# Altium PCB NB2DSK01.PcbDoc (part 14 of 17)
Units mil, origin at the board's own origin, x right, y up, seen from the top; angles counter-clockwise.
Board outline 11815 x 6500.03 mil, 8 copper layers (Top Layer, MidLayer1, MidLayer2, GND, PWR, MidLayer3, MidLayer4, Bottom Layer), stack 74.62 mil thick; 798 components, 1002 nets, 3927 pads, 3182 vias.
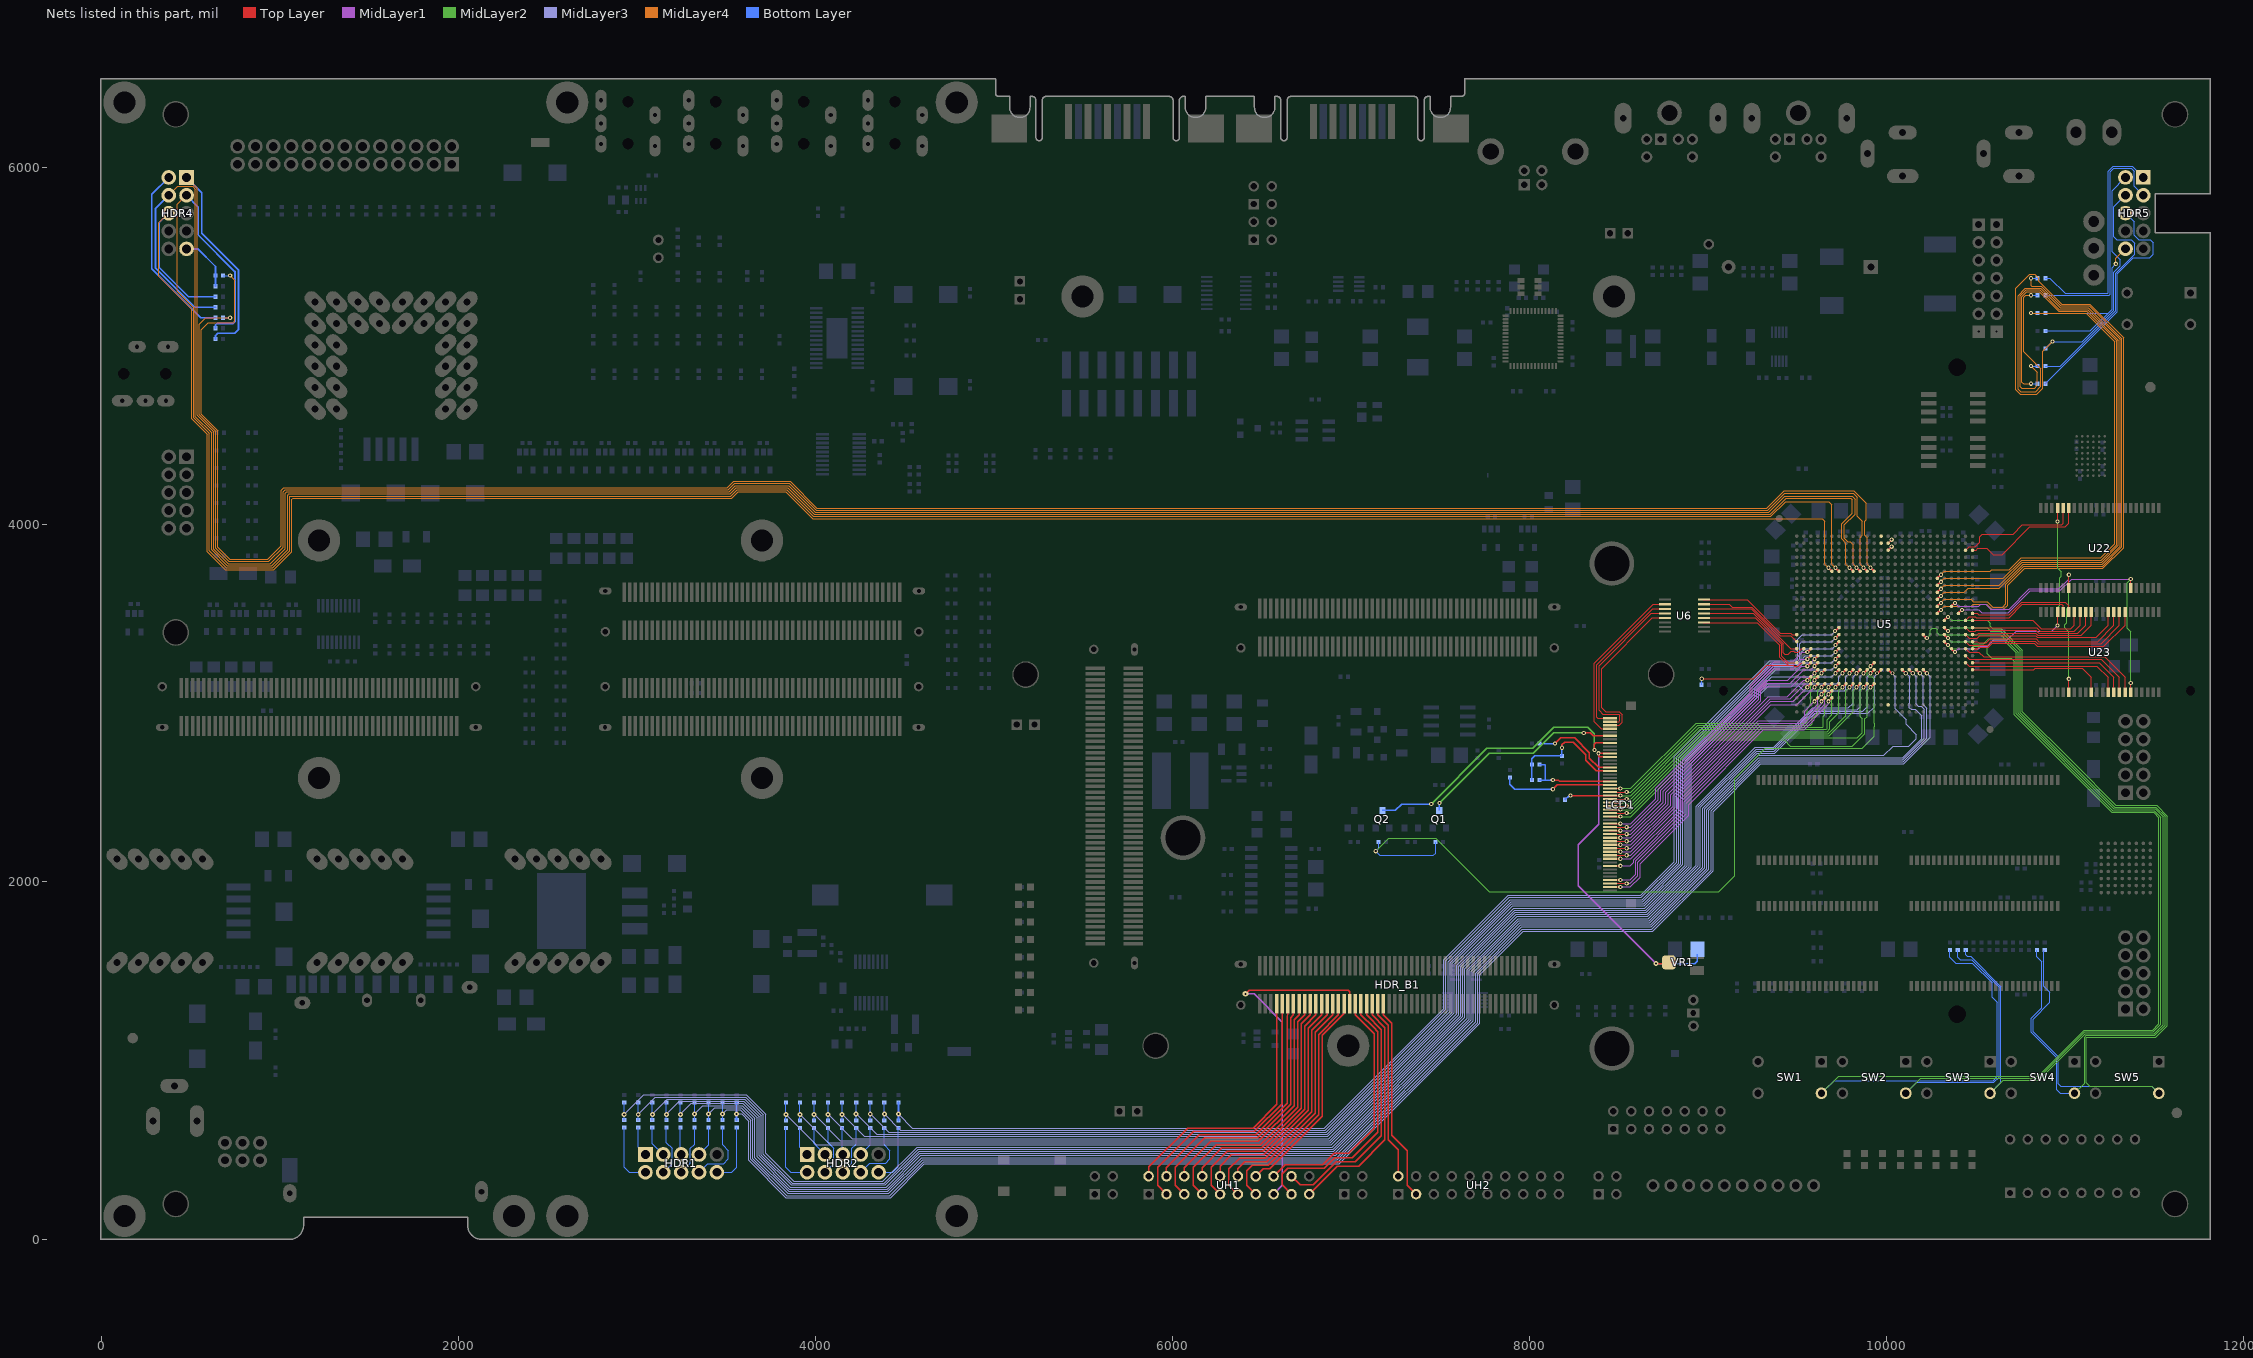
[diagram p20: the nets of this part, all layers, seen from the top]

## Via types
v1: diameter 23.62, hole 11.81, Top Layer to Bottom Layer, tented both sides, 1950 vias
v2: diameter 27.56, hole 11.81, Top Layer to Bottom Layer, tented both sides, 679 vias
v3: diameter 23.62, hole 11.81, Top Layer to Bottom Layer, 194 vias
v4: diameter 31.5, hole 11.81, Top Layer to Bottom Layer, tented both sides, 178 vias
v5: diameter 21.65, hole 11.81, Top Layer to Bottom Layer, tented both sides, 67 vias
v6: diameter 23.62, hole 11.81, Top Layer to Bottom Layer, tented bottom, 53 vias
v7: diameter 26, hole 11.81, Top Layer to Bottom Layer, tented both sides, 21 vias
v8: diameter 26, hole 11.81, Top Layer to Bottom Layer, 13 vias
v9: diameter 28, hole 11.81, Top Layer to Bottom Layer, 8 vias
v10: diameter 25.59, hole 11.81, Top Layer to Bottom Layer, tented both sides, 7 vias
v11: diameter 39.37, hole 11.81, Top Layer to Bottom Layer, tented both sides, 5 vias
v12: diameter 30, hole 11.81, Top Layer to Bottom Layer, 3 vias
v13: diameter 30, hole 11.81, Top Layer to Bottom Layer, tented both sides, 2 vias
v14: diameter 23, hole 11.81, Top Layer to Bottom Layer, tented both sides, 1 vias
v15: diameter 26.56, hole 11.81, Top Layer to Bottom Layer, tented both sides, 1 vias

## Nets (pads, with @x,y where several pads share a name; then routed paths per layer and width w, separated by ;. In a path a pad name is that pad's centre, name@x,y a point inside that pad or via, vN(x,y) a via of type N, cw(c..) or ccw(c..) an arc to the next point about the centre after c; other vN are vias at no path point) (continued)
SRAM.D19: U5.Y26 U23.10 | length 772.5
  Top Layer w5: U5.Y26@10480.32,3188.98 10543.31,3188.98 10562.99,3188.98 10822.83,3188.98 10830.71,3196.85 11094.49,3196.85 11145.67,3145.67 U23.10@11145.67,3062.99
SRAM.D20: U5.W25 U23.13 | length 916.1
  Top Layer w5: U5.W25@10440.95,3228.35 10460.63,3208.66 10543.31,3208.66 10562.99,3208.66 11177.17,3208.66 11240.16,3145.67 U23.13@11240.16,3062.99
SRAM.D21: U5.W26 U23.14 | length 908.3
  Top Layer w5: U5.W26@10480.32,3228.35 10543.31,3228.35 10562.99,3228.35 11188.98,3228.35 11271.66,3145.67 U23.14@11271.65,3062.99
SRAM.D22: U5.V25 U23.15 | length 997
  Top Layer w5: U5.V25@10440.95,3267.72 10462.5,3246.16 10541.44,3246.16 10543.31,3248.03 10562.99,3248.03 11200.79,3248.03 11303.15,3145.67 U23.15@11303.15,3062.99
SRAM.D23: U5.U25 U23.16 | length 1043.2
  Top Layer w5: U5.U25@10440.95,3307.09 10460.63,3287.4 10516.39,3287.4 10543.34,3260.45 11219.86,3260.45 11334.65,3145.67 U23.16@11334.65,3062.99
SRAM.D24: U5.U26 U23.29 | length 998.3
  Top Layer w5: U5.U26@10480.32,3307.09 10507.87,3307.09 10515.75,3314.96 10567.6,3314.96 10590.09,3337.45 10824.72,3337.45 10843.27,3318.9 11216.54,3318.9 11334.65,3437.01 U23.29@11334.65,3511.81
SRAM.D25: U5.T25 U23.30 | length 1001.4
  Top Layer w5: U5.T25@10440.95,3346.46 10460.63,3326.77 10543.31,3326.77 10562.99,3326.77 10565.27,3326.77 10585.95,3347.45 10832.44,3347.45 10845.24,3334.65 11200.79,3334.65 11303.15,3437.01 U23.30@11303.15,3511.81
SRAM.D26: U5.T26 U23.31 | length 922.6
  Top Layer w5: U5.T26@10480.32,3346.46 10507.87,3346.46 10515.75,3338.58 10543.31,3338.58 10556.81,3338.58 10579.68,3361.45 10837.06,3361.45 10852.06,3346.46 11181.1,3346.46 11271.65,3437.01 U23.31@11271.65,3511.81
SRAM.D27: U5.R25 U23.32 | length 918
  Top Layer w5: U5.R25@10440.95,3385.83 10460.63,3366.14 10507.87,3366.14 10519.69,3377.95 10543.31,3377.95 10562.99,3377.95 10834.65,3377.95 10842.52,3370.08 11173.23,3370.08 11240.16,3437.01 U23.32@11240.16,3511.81
SRAM.D28: U5.R26 U23.35 | length 771.1
  Top Layer w5: U5.R26@10480.32,3385.83 10507.87,3385.83 10515.75,3393.7 10543.31,3393.7 10562.99,3393.7 10834.65,3393.7 10846.46,3381.89 11090.55,3381.89 11145.67,3437.01 U23.35@11145.67,3511.81
SRAM.D29: U5.P25 U23.36 | length 782.3
  Top Layer w5: U5.P25@10440.95,3425.2 10460.63,3405.51 10496.06,3405.51 10500,3409.45 10543.31,3409.45 10562.99,3409.45 10834.65,3409.45 10850.39,3393.7 11070.87,3393.7 11114.17,3437.01 U23.36@11114.17,3511.81
SRAM.D30: U5.P26 U23.37 | length 698.4
  Top Layer w5: U5.P26@10480.32,3425.2 10543.31,3425.2 10562.99,3425.2 10838.58,3425.2 10858.27,3405.51 11051.18,3405.51 11082.68,3437.01 U23.37@11082.68,3511.81
SRAM.D31: U5.N26 U23.38 | length 673.4
  Top Layer w5: U5.N26@10480.32,3464.57 10543.31,3464.57 10562.99,3464.57 10818.9,3464.57 10866.14,3417.32 11031.5,3417.32 11051.18,3437.01 U23.38@11051.18,3511.81
SRAM.NBE0: U5.C26 U22.39 | length 717
  Top Layer w5: U5.C26@10480.32,3858.27 10500,3858.27 10510.81,3869.08 10560.78,3869.08 10595.86,3834 10647,3834 10801.19,3988.19 11000,3988.19 11019.69,4007.87 U22.39@11019.69,4094.49
SRAM.NBE1: U5.C25 U22.40 | length 714.3
  Top Layer w5: U5.C25@10440.95,3858.27 10460.63,3877.95 10496.06,3877.95 10519.69,3901.58 10519.69,3933.07 10535.43,3948.82 10543.31,3948.82 10562.99,3948.82 10708.66,3948.82 10759.84,4000 10980.32,4000 10988.19,4007.87 U22.40@10988.19,4094.49
SRAM.NBE2: U5.M26 U23.39 | length 615.6
  Top Layer w5: U5.M26@10480.32,3503.94 10507.87,3503.94 10515.75,3496.06 10543.31,3496.06 10562.99,3496.06 10685.04,3496.06 10755.91,3566.93 11000,3566.93 11019.69,3547.24 U23.39@11019.69,3511.81
SRAM.NBE3: U5.N25 U23.40 | length 626.7
  Top Layer w5: U5.N25@10440.95,3464.57 10460.63,3484.25 10496.06,3484.25 10500,3480.32 10543.31,3480.32 10562.99,3480.32 10685.04,3480.32 10759.84,3555.12 10980.32,3555.12 10988.19,3547.24 U23.40@10988.19,3511.81
SRAM.NCS: U5.L23 U22.6 U23.6 | length 1535.7
  Top Layer w5: U23.6@11019.69,3062.99 v1(11019.69,3137.8) ; U22.6@11019.69,3645.67 v1(11019.69,3720.47)
  Top Layer w7.87: U5.L23@10362.2,3543.31 v1(10381.89,3562.99)
  MidLayer1 w5: v1(10381.89,3562.99) 10401.58,3543.31 10515.75,3543.31 10527.56,3555.12 10543.31,3555.12 10555.12,3555.12 10582.68,3527.56 10685.04,3527.56 10799.21,3641.73 10964.57,3641.73 11019.69,3696.85 v1(11019.69,3720.47)
  MidLayer2 w5: v1(11019.69,3137.8) 11019.69,3401.58 10996.07,3425.2 10996.07,3440.95 11007.88,3452.76 11007.88,3531.5 11019.69,3543.31 v1(11019.69,3720.47)
SRAM.NOE: U5.U23 U22.41 U23.41 | length 1413.2
  Top Layer w5: v1(10956.7,3437.01) U23.41@10956.69,3511.81 ; v1(10956.69,4019.69) U22.41@10956.69,4094.49
  Top Layer w7.87: U5.U23@10362.2,3307.09 v1(10381.89,3287.4)
  MidLayer1 w5: v1(10381.89,3287.4) 10401.58,3307.09 10515.75,3307.09 ; 10515.75,3307.09 10527.56,3318.9 10543.31,3318.9 10562.99,3318.9 10600.55,3356.45 10675.35,3356.45 10724.41,3405.51 10925.2,3405.51 v1(10956.7,3437.01)
  MidLayer2 w5: v1(10956.7,3437.01) 10956.7,3539.37 10968.51,3551.18 10968.51,3704.73 10976.38,3712.6 10976.38,3736.22 10956.69,3755.91 v1(10956.69,4019.69)
SRAM.NWE: U5.M24 U22.17 U23.17 | length 1758.9
  Top Layer w5: U23.17@11366.14,3062.99 v1(11366.14,3114.17) ; U22.17@11366.14,3645.67 v1(11366.14,3696.85)
  Top Layer w7.87: U5.M24@10401.58,3503.94 v1(10421.26,3523.62)
  MidLayer1 w5: v1(10421.26,3523.62) 10515.75,3523.62 10531.5,3507.87 10543.31,3507.87 10562.99,3507.87 10681.1,3507.87 10803.15,3629.92 10968.5,3629.92 11035.43,3696.85 v1(11366.14,3696.85)
  MidLayer2 w5: v1(11366.14,3114.17) 11366.14,3401.58 11346.46,3421.26 11346.46,3677.17 v1(11366.14,3696.85)
SW0: R153.2 SW1.3 U5.T22 | length 6921.8
  Top Layer w7.87: U5.T22@10322.83,3346.46 v1(10342.52,3326.77)
  MidLayer2 w5: SW1.3@9633.86,816.93 9730.32,913.39 10847.1,913.39 11104.62,1170.9 11489.53,1170.9 11523.62,1204.99 11523.62,2359.91 11494.23,2389.3 11260.31,2389.3 10996.06,2653.54 10712.6,2937.01 10712.6,3237.5 10698.41,3251.68 10588.75,3251.68 10562.99,3277.44 10562.99,3318.9 10543.31,3318.9 10484.25,3318.9 10472.44,3307.09 10362.21,3307.09 v1(10342.52,3326.77)
  Bottom Layer w5: SW1.3@9633.86,816.93 9704.88,887.95 10596.31,887.95 10619.61,911.25 10619.61,1326 10590.5,1355.11 10590.5,1435.17 10479.65,1546.02 10385.98,1546.02 10353.41,1578.6 R153.2@10353.41,1618.11
SW1: R154.2 SW2.3 U5.R22 | length 6013
  Top Layer w7.87: U5.R22@10322.83,3385.83 v1(10342.52,3366.14)
  MidLayer2 w5: SW2.3@10106.3,816.93 10190.95,901.58 10849.44,901.58 11108.76,1160.9 11493.67,1160.9 11535.43,1202.66 11535.43,2362.24 11498.37,2399.3 11266.06,2399.3 10724.41,2940.95 10724.41,3283.47 10646.42,3361.45 10570.12,3361.45 10543.31,3334.65 10484.25,3334.65 10472.44,3346.46 10362.21,3346.46 v1(10342.52,3366.14)
  Bottom Layer w5: SW2.3@10106.3,816.93 10167.32,877.95 10600.45,877.95 10629.61,907.11 10629.61,1410.2 10474.7,1565.11 10410.89,1565.11 10397.7,1578.3 R154.2@10397.7,1618.11
SW2: R155.1 SW3.3 U5.R19 | length 5246.7
  Top Layer w7.87: U5.R19@10204.72,3385.83 v1(10224.41,3366.14)
  MidLayer2 w5: v1(10224.41,3366.14) 10244.09,3385.83 10244.09,3409.84 10255.91,3421.65 10274.02,3421.65 10283.07,3412.6 10283.07,3396.33 10293.58,3385.83 10543.31,3385.83 10562.99,3385.83 10637.8,3385.83 10736.22,3287.4 10736.22,2944.88 11019.69,2661.42 11271.8,2409.3 11502.52,2409.3 11547.24,2364.57 11547.24,1200.33 11497.82,1150.9 11112.9,1150.9 10851.77,889.77 10651.58,889.77 SW3.3@10578.74,816.93
  Bottom Layer w5: R155.1@10441.99,1618.11 10441.99,1593.01 10451,1584 10469.95,1584 10639.61,1414.35 10639.61,877.8 SW3.3@10578.74,816.93
SW3: R156.2 SW4.3 U5.P22 | length 4865
  Top Layer w7.87: U5.P22@10322.83,3425.2 v1(10342.52,3405.51)
  MidLayer2 w5: v1(10342.52,3405.51) 10362.21,3425.2 10543.31,3425.2 10562.99,3425.2 10582.68,3405.51 10637.8,3405.51 10748.03,3295.28 10748.03,2948.82 11277.55,2419.3 11506.66,2419.3 11559.06,2366.9 11559.06,1198 11501.96,1140.9 11117.04,1140.9 11108,1131.86 11108,873.75 SW4.3@11051.18,816.93
  Bottom Layer w5: R156.2@10840.61,1618.11 10840.61,1581.82 10869,1553.42 10869,1295.8 10809.21,1236.02 10809.21,1157.69 10950.94,1015.95 10950.94,836.19 10970.2,816.93 SW4.3@11051.18,816.93
SW4: R157.1 SW5.3 U5.N22 | length 5713.7
  Top Layer w7.87: U5.N22@10322.83,3464.57 v1(10342.52,3484.25)
  MidLayer2 w5: v1(10342.52,3484.25) 10362.21,3464.57 10543.31,3464.57 10562.99,3464.57 10578.74,3448.82 10578.74,3433.07 10594.49,3417.32 10641.73,3417.32 10759.84,3299.21 10759.84,2952.76 11043.31,2669.29 11283.3,2429.3 11510.8,2429.3 11570.87,2369.23 11570.87,1195.67 11506.1,1130.9 11121.18,1130.9 11118,1127.72 11118,877 11138,857 11483.55,857 SW5.3@11523.62,816.93
  Bottom Layer w5: R157.1@10884.9,1618.11 10879,1612.21 10879,1417 10914,1382 10914,1326.66 10819.21,1231.87 10819.21,1161.83 10960.94,1020.1 10960.94,870.06 10974,857 11483.55,857 SW5.3@11523.62,816.93
TALK#.MASTER.CNCT: HDR4.9 R296.2 R302.1 | length 313.1
  Bottom Layer w10: HDR4.9@477.95,5545.67 541.46,5545.67 640.24,5446.9 R302.1@640.24,5396.06 R296.2@640.24,5337.01
TALK#.MASTER.MODE: HDR4.6 R297.1 U5.F6 | length 12558.6
  Top Layer w7.87: v1(9673.23,3759.84) U5.F6@9692.91,3740.16
  MidLayer4 w5: HDR4.6@377.95,5745.67 323,5690.72 323,5392.13 508,5207.13 508,4593.52 594.49,4507.04 594.49,3849.56 696.01,3748.03 965.26,3748.03 1067.68,3850.45 1067.68,4142.45 1074.83,4149.61 3531.5,4149.61 3566.93,4185.04 3834.65,4185.04 3984.25,4035.43 9637.8,4035.43 9653.54,4019.69 9653.54,4000 9653.54,3779.53 v1(9673.23,3759.84)
  Bottom Layer w10: HDR4.6@377.95,5745.67 323.68,5691.4 323.68,5443.45 489.18,5277.95 R297.1@640.24,5277.95
TALK#.MASTER.TCK: HDR4.3 R299.1 U5.F7 | length 13017.8
  Top Layer w7.87: v1(9712.6,3759.84) U5.F7@9732.28,3740.16
  MidLayer4 w5: HDR4.3@477.95,5845.67 427,5794.72 427,5308.14 518,5217.14 518,4600.23 606.3,4511.93 606.3,3854.45 700.9,3759.84 960.07,3759.84 1055.68,3855.45 1055.68,4159.13 1057.97,4161.42 3526.6,4161.42 3562.04,4196.85 3839.54,4196.85 3989.14,4047.24 9350.39,4047.24 9433.07,4129.92 9675.05,4129.92 9692.91,4112.06 9692.91,4019.69 9692.91,4000 9692.91,3779.53 v1(9712.6,3759.84)
  Bottom Layer w10: HDR4.3@477.95,5845.67 543.68,5779.94 543.68,5623.45 748.68,5418.45 748.68,5138.45 738.68,5128.45 648.68,5128.45 640.24,5120.01 R299.1@640.24,5100.79
TALK#.MASTER.TDI: HDR4.1 R300.1 U5.F10 | length 13456.1
  Top Layer w7.87: v1(9830.71,3759.84) U5.F10@9850.39,3740.16
  MidLayer4 w5: HDR4.1@477.95,5945.67 539,5884.62 539,4612.63 629.92,4521.71 629.92,3864.23 710.69,3783.47 947.69,3783.47 1031.68,3867.45 1031.68,4176.45 1040.27,4185.04 3516.82,4185.04 3552.25,4220.47 3849.32,4220.47 3998.93,4070.87 9338.58,4070.87 9429.17,4161.45 9806.68,4161.45 9823.68,4144.45 9823.68,4060.35 9762.68,3999.35 9762.68,3925.45 9782.02,3906.12 9794.67,3906.12 9811.02,3889.76 9811.02,3779.53 v1(9830.71,3759.84)
  Bottom Layer w5: HDR4.1@473.62,5944.88 477.95,5944.88 478.74,5944.88 HDR4.1@483.07,5944.88
  Bottom Layer w10: HDR4.1@477.95,5945.67 478.74,5944.88 563.68,5859.94 563.68,5633.45 768.68,5428.45 768.68,5093.45 748.68,5073.45 653.68,5073.45 640.24,5060.01 R300.1@640.24,5041.73
TALK#.MASTER.TDO: HDR4.2 R301.1 | length 1026.3
  Bottom Layer w5: HDR4.2@377.95,5945.67 HDR4.2@383.07,5945.67
  Bottom Layer w10: HDR4.2@377.95,5945.67 283.68,5851.4 283.68,5433.45 557.29,5159.84 R301.1@640.24,5159.84
TALK#.MASTER.TMS: HDR4.4 R298.1 U5.F9 | length 13241.1
  Top Layer w7.87: v1(9791.34,3759.84) U5.F9@9811.02,3740.16
  MidLayer4 w5: HDR4.4@377.95,5845.67 429.28,5897 512,5897 528,5881 528,4606.93 618.11,4516.82 618.11,3859.34 705.8,3771.65 955.88,3771.65 1043.82,3859.59 1043.82,4166.59 1050.46,4173.23 3521.71,4173.23 3557.14,4208.66 3844.43,4208.66 3994.04,4059.06 9346.46,4059.06 9435.85,4148.45 9798.56,4148.45 9806.68,4140.33 9806.68,4064.45 9747.17,4004.94 9747.17,3922.43 9771.65,3897.94 9771.65,3779.53 v1(9791.34,3759.84)
  Bottom Layer w10: HDR4.4@377.95,5845.67 304.48,5772.2 304.48,5437.66 523.24,5218.9 R298.1@640.24,5218.9
TALK#.SLAVE.CNCT: HDR5.10 R303.2 R309.1 | length 1147.1
  MidLayer4 w5: v1(11283,5462) 11283,5492.06 HDR5.10@11337.01,5546.06
  Bottom Layer w5: R303.2@10887.76,5086 11140.61,5086 11261.68,5207.07 11261.68,5440.68 v1(11283,5462) ; R309.1@10887.76,5186 11240.61,5186
TALK#.SLAVE.MODE: HDR5.6 R308.2 | length 1362.5
  Bottom Layer w5: R308.2@10887.76,4790.72 11291.68,5194.64 11291.68,5406.4 11380.28,5495 11472,5495 11493,5516 11493,5579 11476,5596 11411,5596 11386,5621 11386,5697.07 HDR5.6@11337.01,5746.06
TALK#.SLAVE.TCK: HDR5.3 R306.1 | length 1359.3
  Bottom Layer w5: R306.1@10887.76,5286 11247,5286 11251.68,5290.68 11251.68,5977.6 11272.13,5998.04 11369.96,5998.04 11387,5981 11387,5896.07 HDR5.3@11437.01,5846.06 HDR5.3@11436.94,5846.06
TALK#.SLAVE.TDI: HDR5.1 R305.1 | length 1304.1
  Bottom Layer w5: R305.1@10887.76,5381.27 10913,5381.27 10998.28,5296 11237,5296 11241.68,5300.68 11241.68,5981.74 11267.98,6008.04 11375.03,6008.04 HDR5.1@11437.01,5946.06
TALK#.SLAVE.TDO: HDR5.2 R304.2 U5.M21 | length 5557.9
  Top Layer w7.87: U5.M21@10283.46,3503.94 v1(10303.15,3523.62)
  MidLayer4 w5: v1(10303.15,3523.62) 10322.84,3543.31 10472.44,3543.31 10484.25,3555.12 10543.31,3555.12 10559.06,3555.12 10586.61,3527.56 10653.54,3527.56 10677.17,3551.18 10677.17,3661.42 10771.65,3755.91 11210.66,3755.91 11327,3872.25 11327,5046.71 11137.71,5236 10979.57,5236 10852,5363.57 10852,5380.52 10830,5402.52 10800.52,5402.52 10723.55,5325.55 10723.55,4756.62 10748.2,4731.97 10838.97,4731.97 10872.2,4765.2 10872.2,4971.2 v1(10927.52,5026.52)
  Bottom Layer w5: R304.2@10887.76,4987.57 v1@10927.11,5026.92 ; v1(10927.52,5026.52) 11095.27,5026.52 11271.68,5202.93 11271.68,5414.68 11308.07,5451.07 11308.07,5483.93 11261.68,5530.32 11261.68,5870.74 HDR5.2@11337.01,5946.06
TALK#.SLAVE.TMS: HDR5.4 R307.2 | length 1336.2
  Bottom Layer w5: R307.2@10887.76,4889.15 10972.05,4889.15 11281.68,5198.78 11281.68,5410.54 11388,5516.86 11388,5578 11370,5596 11289,5596 11271.68,5613.32 11271.68,5780.74 HDR5.4@11337.01,5846.06
TALK.MASTER.CNCT: R302.2 U5.F12 | length 11934.9
  Top Layer w7.87: v1(9909.45,3759.84) U5.F12@9929.13,3740.16
  MidLayer4 w5: v1(722.36,5396.06) 748.6,5369.83 748.6,5139.73 741.9,5133.03 598.88,5133.03 559,5093.15 559,4620.92 653.54,4526.37 653.54,3874.02 720.47,3807.09 933.32,3807.09 1008.68,3882.45 1008.68,4194.01 1023.33,4208.66 3507.03,4208.66 3542.47,4244.1 3859.11,4244.1 4008.71,4094.49 9328.8,4094.49 9425.76,4191.45 9816.41,4191.45 9885.83,4122.03 9885.83,4027.56 9877.95,4019.69 9877.95,4000 9877.95,3940.95 9889.76,3929.13 9889.76,3779.53 v1(9909.45,3759.84)
  Bottom Layer w5: R302.2@682.6,5396.06 v1(722.36,5396.06)
TALK.MASTER.TDO: R301.2 U5.F11 | length 11663.6
  Top Layer w7.87: v1(9870.08,3759.84) U5.F11@9889.76,3740.16
  MidLayer4 w5: v1(722.36,5159.84) 585.86,5159.84 562.99,5136.97 549,5122.98 549,4616.78 641.73,4524.04 641.73,3869.12 715.58,3795.28 939.5,3795.28 1019.68,3875.45 1019.68,4185.45 1031.08,4196.85 3511.93,4196.85 3547.36,4232.28 3854.21,4232.28 4003.82,4082.68 9333.69,4082.68 9427.47,4176.45 9812.68,4176.45 9834.68,4154.45 9834.68,4047.21 9862.2,4019.69 9862.2,4000 9862.2,3940.95 9850.39,3929.13 9850.39,3779.53 v1(9870.08,3759.84)
  Bottom Layer w5: R301.2@682.6,5159.84 v1(722.36,5159.84)
TALK.SLAVE.CNCT: R309.2 U5.G21 | length 2778.9
  Top Layer w7.87: U5.G21@10283.46,3700.79 v1(10303.15,3720.47)
  MidLayer4 w5: v1(10303.15,3720.47) 10322.84,3740.16 10543.31,3740.16 10562.99,3740.16 10578.74,3740.16 10586.61,3748.03 10685.04,3748.03 10751.97,3814.96 11199,3814.96 11277,3892.96 11277,5026 11117,5186 v1(10808,5186)
  Bottom Layer w5: v1(10808,5186) R309.2@10845.4,5186
TALK.SLAVE.MODE: R308.1 U5.H21 | length 3465
  Top Layer w7.87: U5.H21@10283.46,3661.42 v1(10303.15,3681.1)
  MidLayer4 w5: v1(10303.15,3681.1) 10322.84,3700.79 10543.31,3700.79 10562.99,3700.79 10653.54,3700.79 10755.91,3803.15 11201.33,3803.15 11287,3888.82 11287,5030.14 11121.14,5196 10963,5196 10853,5306 10784.92,5306 10757.2,5278.29 10757.2,4799.84 10766.32,4790.72 v1(10808,4790.72)
  Bottom Layer w5: v1(10808,4790.72) R308.1@10845.4,4790.72
TALK.SLAVE.TCK: R306.2 U5.K21 | length 4302.2
  Top Layer w7.87: U5.K21@10283.46,3582.68 v1(10303.15,3602.36)
  MidLayer4 w5: v1(10303.15,3602.36) 10322.84,3622.05 10433.07,3622.05 10456.69,3645.67 10543.31,3645.67 10562.99,3645.67 10629.92,3645.67 10763.78,3779.53 11205.99,3779.53 11307,3880.54 11307,5038.43 11129.43,5216 10971.28,5216 10861.28,5326 10776.63,5326 10735.2,5284.57 10735.2,4760.97 10749.2,4746.97 10833.75,4746.97 10862.2,4775.43 10862.2,4874.72 10767.2,4969.72 10767.2,5274.14 10779.06,5286 v1(10808,5286)
  Bottom Layer w5: v1(10808,5286) R306.2@10845.4,5286
TALK.SLAVE.TDI: R305.2 U5.L21 | length 3149
  Top Layer w7.87: U5.L21@10283.46,3543.31 v1(10303.15,3562.99)
  MidLayer4 w5: v1(10303.15,3562.99) 10322.84,3582.68 10472.44,3582.68 10484.25,3570.87 10543.31,3570.87 10559.06,3570.87 10562.99,3570.87 10594.49,3539.37 10649.61,3539.37 10667.17,3556.93 10667.17,3667.17 10767.72,3767.72 11208.32,3767.72 11317,3876.39 11317,5042.57 11133.57,5226 10975.43,5226 10865.43,5336 10812,5336 10808,5340 v1(10808,5381.27)
  Bottom Layer w5: v1(10808,5381.27) R305.2@10845.4,5381.27
TALK.SLAVE.TMS: R307.1 U5.J21 | length 3728.3
  Top Layer w7.87: U5.J21@10283.46,3622.05 v1(10303.15,3641.73)
  MidLayer4 w5: v1(10303.15,3641.73) 10322.84,3661.42 10543.31,3661.42 10562.99,3661.42 10629.92,3661.42 10759.84,3791.34 11203.66,3791.34 11297,3884.68 11297,5034.28 11125.28,5206 10967.14,5206 10857.14,5316 10780.77,5316 10747.2,5282.43 10747.2,4773.32 10755.33,4765.19 10827.93,4765.19 10843.75,4781.01 10843.75,4853.4 v1(10808,4889.15)
  Bottom Layer w5: v1(10808,4889.15) R307.1@10845.4,4889.15
TFT#.BLUE0: LCD1.22 U5.AB12 | length 1951.6
  Top Layer w5: LCD1.22@8448.82,2366.14 v1(8507.87,2366.14)
  Top Layer w7.87: v1(9909.45,3090.55) U5.AB12@9929.13,3110.24
  MidLayer2 w5: v1(8507.87,2366.14) 8566.93,2366.14 8996.06,2795.28 9425.2,2795.28 9460.63,2759.84 9807.09,2759.84 9877.95,2830.71 9877.95,2870.08 9877.95,2889.76 9877.95,2913.39 9889.76,2925.2 9889.76,3070.87 v1(9909.45,3090.55)
TFT#.BLUE1: LCD1.23 U5.AB11 | length 1895.8
  Top Layer w5: LCD1.23@8448.82,2385.83 v1(8543.31,2385.83)
  Top Layer w7.87: v1(9870.08,3090.55) U5.AB11@9889.76,3110.24
  MidLayer2 w5: v1(8543.31,2385.83) 8566.93,2385.83 8988.19,2807.09 9834.09,2807.09 9862.2,2835.2 9862.2,2913.39 9850.39,2925.2 9850.39,3070.87 v1(9870.08,3090.55)
TFT#.BLUE2: LCD1.24 U5.AB10 | length 1790.5
  Top Layer w5: LCD1.24@8448.82,2405.51 v1(8507.87,2405.51)
  Top Layer w7.87: v1(9830.71,3090.55) U5.AB10@9850.39,3110.24
  MidLayer2 w5: v1(8507.87,2405.51) 8566.93,2405.51 8594.49,2433.07 ; 8574.8,2413.39 8980.32,2818.9 9677.17,2818.9 9811.02,2952.76 9811.02,3070.87 v1(9830.71,3090.55)
TFT#.BLUE3: LCD1.25 U5.AB9 | length 1727.6
  Top Layer w5: LCD1.25@8448.82,2425.2 v1(8543.31,2425.2)
  Top Layer w7.87: v1(9791.34,3090.55) U5.AB9@9811.02,3110.24
  MidLayer2 w5: v1(8543.31,2425.2) 8566.93,2425.2 8972.44,2830.71 9670.94,2830.71 9771.65,2931.42 9771.65,3070.87 v1(9791.34,3090.55)
TFT#.BLUE4: LCD1.26 U5.AB8 | length 1693
  Top Layer w5: LCD1.26@8448.82,2444.88 v1(8507.87,2444.88)
  Top Layer w7.87: v1(9751.97,3090.55) U5.AB8@9771.65,3110.24
  MidLayer2 w5: v1(8507.87,2444.88) 8566.93,2444.88 8964.57,2842.52 9665.35,2842.52 9681.1,2858.27 9681.1,2870.08 9681.1,2889.76 9681.1,2897.64 9732.28,2948.82 9732.28,3070.87 v1(9751.97,3090.55)
TFT#.CL1: LCD1.29 U5.AB5 | length 1545.8
  Top Layer w5: LCD1.29@8448.82,2503.94 v1(8543.31,2503.94)
  Top Layer w7.87: v1(9633.86,3090.55) U5.AB5@9653.54,3110.24
  MidLayer2 w5: v1(8543.31,2503.94) 8566.93,2503.94 8940.95,2877.95 9574.8,2877.95 9582.68,2885.83 9582.68,2901.58 9582.68,2913.39 9614.17,2944.88 9614.17,3070.87 v1(9633.86,3090.55)
TFT#.CL2: LCD1.30 U5.Y5 | length 1611.8
  Top Layer w5: LCD1.30@8448.82,2523.62 v1(8507.87,2523.62)
  Top Layer w7.87: v1(9633.86,3169.29) U5.Y5@9653.54,3188.98
  MidLayer2 w5: v1(8507.87,2523.62) 8566.93,2523.62 8933.07,2889.76 9547.24,2889.76 9555.12,2897.64 9555.12,2913.39 9555.12,2976.38 9574.8,2996.06 9574.8,3141.73 9582.68,3149.61 9614.17,3149.61 v1(9633.86,3169.29)
TFT#.CL3: LCD1.3 U5.AC6 | length 1797
  Top Layer w5: LCD1.3@8448.82,1992.13 v1(8543.31,1992.13)
  Top Layer w7.87: v1(9673.23,3051.18) U5.AC6@9692.91,3070.87
  MidLayer1 w5: v1(8543.31,1992.13) 8562.99,1992.13 8606.3,2035.43 8606.3,2110.24 8877.95,2381.89 8877.95,2440.95 9300.46,2863.45 9532.74,2863.45 9582.68,2913.39 9582.68,2925.2 9653.54,2996.06 9653.54,3031.5 v1(9673.23,3051.18)
TFT#.DISP_ON: LCD1.2 U5.AD6 | length 1774.8
  Top Layer w5: LCD1.2@8448.82,1972.44 v1(8507.87,1972.44)
  Top Layer w7.87: v1(9673.23,3011.81) U5.AD6@9692.91,3031.5
  MidLayer1 w5: v1(8507.87,1972.44) 8562.99,1972.44 8618.11,2027.56 8618.11,2102.36 8889.76,2374.02 8889.76,2433.07 9309.15,2852.45 9537.12,2852.45 9594.49,2909.82 9594.49,2917.32 9673.23,2996.06 v1(9673.23,3011.81)
TFT#.GREEN0: LCD1.15 U5.Y4 | length 1627.8
  Top Layer w5: LCD1.15@8448.82,2228.35 v1(8543.31,2228.35)
  Top Layer w7.87: v1(9594.49,3169.29) U5.Y4@9614.17,3188.98
  MidLayer1 w5: v1(8543.31,2228.35) 8566.93,2228.35 8775.03,2436.45 8775.03,2495.5 9283.46,3003.94 9295.28,3015.75 9295.28,3066.93 9322.83,3094.49 9413.39,3094.49 9433.07,3094.49 9464.57,3094.49 9519.69,3149.61 9574.8,3149.61 v1(9594.49,3169.29)
TFT#.GREEN1: LCD1.16 U5.W4 | length 1633.7
  Top Layer w5: LCD1.16@8448.82,2248.03 v1(8507.87,2248.03)
  Top Layer w7.87: v1(9594.49,3208.66) U5.W4@9614.17,3228.35
  MidLayer1 w5: v1(8507.87,2248.03) 8566.93,2248.03 8761.11,2442.21 8761.11,2501.27 9283.46,3023.62 9283.46,3070.87 9326.77,3114.17 9413.39,3114.17 9433.07,3114.17 9460.63,3114.17 9535.43,3188.98 9574.8,3188.98 v1(9594.49,3208.66)
TFT#.GREEN2: LCD1.17 U5.W3 | length 1583.9
  Top Layer w5: LCD1.17@8448.82,2267.72 v1(8543.31,2267.72)
  Top Layer w7.87: v1(9555.12,3208.66) U5.W3@9574.8,3228.35
  MidLayer1 w5: v1(8543.31,2267.72) 8566.93,2267.72 8747.19,2447.98 8747.19,2507.04 9271.65,3031.5 9271.65,3074.8 9326.77,3129.92 9413.39,3129.92 9433.07,3129.92 9444.88,3129.92 9523.62,3208.66 v1(9555.12,3208.66)
TFT#.GREEN3: LCD1.18 U5.V4 | length 1631.4
  Top Layer w5: LCD1.18@8448.82,2287.4 v1(8507.87,2287.4)
  Top Layer w7.87: v1(9594.49,3248.03) U5.V4@9614.17,3267.72
  MidLayer1 w5: v1(8507.87,2287.4) 8566.93,2287.4 8733.27,2453.75 8733.27,2512.8 9259.84,3039.37 9259.84,3082.68 9370.08,3192.91 9413.39,3192.91 9433.07,3192.91 9480.32,3192.91 9515.75,3228.35 9574.8,3228.35 v1(9594.49,3248.03)
TFT#.GREEN4: LCD1.19 U5.V3 | length 1583.9
  Top Layer w5: LCD1.19@8448.82,2307.09 v1(8543.31,2307.09)
  Top Layer w7.87: v1(9555.12,3248.03) U5.V3@9574.8,3267.72
  MidLayer1 w5: v1(8543.31,2307.09) 8566.93,2307.09 8719.35,2459.51 8719.35,2518.57 9248.03,3047.24 9248.03,3090.55 9370.08,3212.6 9417.32,3212.6 9433.07,3212.6 9476.38,3212.6 9511.81,3248.03 v1(9555.12,3248.03)
TFT#.GREEN5: LCD1.20 U5.U3 | length 1592
  Top Layer w5: LCD1.20@8448.82,2326.77 v1(8507.87,2326.77)
  Top Layer w7.87: v1(9555.12,3287.4) U5.U3@9574.8,3307.09
  MidLayer1 w5: v1(8507.87,2326.77) 8566.93,2326.77 8705.43,2465.28 8705.43,2524.33 9236.22,3055.12 9236.22,3098.43 9371.25,3233.45 9474.02,3233.45 9527.97,3287.4 v1(9555.12,3287.4)
TFT#.LED_C_L: LCD1.45 Q1.3 | length 1164.8
  Top Layer w7.87: v1(8303.15,2834.65) 8340.55,2834.65 8356.3,2818.9 LCD1.45@8448.82,2818.9
  MidLayer2 w7.87: v1(7494.42,2442.2) 7772.69,2720.47 8021.14,2720.47 8135.31,2834.65 v1(8303.15,2834.65)
  Bottom Layer w7.87: Q1.3@7494.42,2400.86 v1(7494.42,2442.2)
TFT#.LED_C_R: LCD1.43 Q2.3 | length 1607.4
  Top Layer w7.87: v1(8362.9,2739.4) 8362.9,2772.2 8370.23,2779.53 LCD1.43@8448.82,2779.53
  MidLayer2 w7.87: v1(7449.14,2436.29) 7760.88,2748.03 8016.26,2748.03 8134.37,2866.14 8326.77,2866.14 8362.9,2830.01 v1(8362.9,2739.4)
  Bottom Layer w7.87: Q2.3@7175.52,2400.86 7248.35,2400.86 7283.79,2436.29 v1(7449.14,2436.29)
TFT#.M: C118.1 LCD1.28 U5.AB6 | length 1877.7
  Top Layer w5: LCD1.28@8448.82,2484.25 v1(8507.87,2484.25)
  Top Layer w7.87: v1(8228.35,2484.25) LCD1.28@8448.82,2484.25 ; v1(9673.23,3090.55) U5.AB6@9692.91,3110.24
  MidLayer2 w5: v1(8507.87,2484.25) 8566.93,2484.25 8948.82,2866.14 9641.73,2866.14 9645.67,2870.08 9645.67,2889.76 9645.67,2929.13 9653.54,2937.01 9653.54,3070.87 v1(9673.23,3090.55)
  Bottom Layer w5: C118.1@8197.83,2460.63 C118.1@8197.83,2461.61
  Bottom Layer w7.87: C118.1@8197.83,2461.61 8220.47,2484.25 v1(8228.35,2484.25)
TFT#.POL: LCD1.27 U5.AB7 | length 1659.3
  Top Layer w5: LCD1.27@8448.82,2464.57 v1(8543.31,2464.57)
  Top Layer w7.87: v1(9712.6,3090.55) U5.AB7@9732.28,3110.24
  MidLayer2 w5: v1(8543.31,2464.57) 8566.93,2464.57 8956.69,2854.33 9661.42,2854.33 9665.35,2858.27 9665.35,2870.08 9665.35,2889.76 9665.35,2909.45 9692.91,2937.01 9692.91,3070.87 v1(9712.6,3090.55)
TFT#.RED0: LCD1.10 U5.AD4 | length 1591.8
  Top Layer w5: LCD1.10@8448.82,2129.92 v1(8507.87,2129.92)
  Top Layer w7.87: v1(9594.49,3011.81) U5.AD4@9614.17,3031.5
  MidLayer1 w5: v1(8507.87,2129.92) 8566.93,2129.92 8842.52,2405.51 8842.52,2464.57 9281.61,2903.66 9517.83,2903.66 9539.37,2925.2 9539.37,2956.69 v1(9594.49,3011.81)
TFT#.RED1: LCD1.11 U5.AB4 | length 1597.9
  Top Layer w5: LCD1.11@8448.82,2149.61 v1(8543.31,2149.61)
  Top Layer w7.87: v1(9594.49,3090.55) U5.AB4@9614.17,3110.24
  MidLayer1 w5: v1(8543.31,2149.61) 8566.93,2149.61 8830.71,2413.39 8830.71,2472.44 9350.39,2992.13 9413.39,2992.13 9433.07,2992.13 9496.06,2992.13 v1(9594.49,3090.55)
TFT#.RED2: LCD1.12 U5.AB3 | length 1550.3
  Top Layer w5: LCD1.12@8448.82,2169.29 v1(8507.87,2169.29)
  Top Layer w7.87: v1(9555.12,3090.55) U5.AB3@9574.8,3110.24
  MidLayer1 w5: v1(8507.87,2169.29) 8566.93,2169.29 8816.79,2419.15 8816.79,2478.21 9350.39,3011.81 9413.39,3011.81 9433.07,3011.81 9476.38,3011.81 v1(9555.12,3090.55)
TFT#.RED3: LCD1.13 U5.AA4 | length 1597.9
  Top Layer w5: LCD1.13@8448.82,2188.98 v1(8543.31,2188.98)
  Top Layer w7.87: v1(9594.49,3129.92) U5.AA4@9614.17,3149.61
  MidLayer1 w5: v1(8543.31,2188.98) 8566.93,2188.98 8802.87,2424.92 8802.87,2483.97 9346.46,3027.56 9417.32,3027.56 9433.07,3027.56 9460.63,3027.56 9543.31,3110.24 9574.8,3110.24 v1(9594.49,3129.92)
TFT#.RED4: LCD1.14 U5.AA3 | length 1550.3
  Top Layer w5: LCD1.14@8448.82,2208.66 v1(8507.87,2208.66)
  Top Layer w7.87: v1(9555.12,3129.92) U5.AA3@9574.8,3149.61
  MidLayer1 w5: v1(8507.87,2208.66) 8566.93,2208.66 8788.95,2430.68 8788.95,2489.74 9336.77,3037.56 9443.07,3037.56 9535.43,3129.92 v1(9555.12,3129.92)
TFT#.STH: LCD1.8 U5.AC5 | length 1682.3
  Top Layer w5: LCD1.8@8448.82,2090.55 v1(8507.87,2090.55)
  Top Layer w7.87: v1(9633.86,3051.18) U5.AC5@9653.54,3070.87
  MidLayer1 w5: v1(8507.87,2090.55) 8562.99,2090.55 8582.68,2110.24 8582.68,2125.99 8854.33,2397.64 8854.33,2456.69 9287.09,2889.45 9519.37,2889.45 9555.12,2925.2 9555.12,2937.01 9614.17,2996.06 9614.17,3031.5 v1(9633.86,3051.18)
TFT#.STV: LCD1.4 U5.AD5 | length 1721.6
  Top Layer w5: LCD1.4@8448.82,2011.81 v1(8507.87,2011.81)
  Top Layer w7.87: v1(9633.86,3011.81) U5.AD5@9653.54,3031.5
  MidLayer1 w5: v1(8507.87,2011.81) 8562.99,2011.81 8594.49,2043.31 8594.49,2118.11 8866.14,2389.76 8866.14,2448.82 9292.78,2875.45 9525.06,2875.45 9570.87,2921.26 9570.87,2933.07 9633.86,2996.06 v1(9633.86,3011.81)
TFT#.V0: LCD1.31 R43.1 | length 618.1
  Top Layer w7.87: v1(8129.92,2519.69) 8153.54,2543.31 LCD1.31@8448.82,2543.31
  Bottom Layer w7.87: R43.1@7889.76,2585.12 7889.76,2547.24 7917.32,2519.69 v1(8129.92,2519.69)
TFT#.V4: LCD1.32 R45.2 R46.2 | length 514.2
  Top Layer w7.87: v1(8129.92,2570.87) 8161.42,2570.87 8169.29,2562.99 LCD1.32@8448.82,2562.99
  Bottom Layer w7.87: R46.2@8054.65,2570.87 v1(8129.92,2570.87) ; R45.2@8054.65,2657.48 8085.72,2657.48 8087.17,2656.03 8087.17,2572.36
TFT#.V5: C115.1 LCD1.35 R45.1 R46.1 | length 713.8
  Top Layer w7.87: v1(8181.1,2751.97) 8181.1,2767.72 8196.85,2783.47 8244.09,2783.47 8314.96,2712.6 8314.96,2681.1 8374.02,2622.05 LCD1.35@8448.82,2622.05
  Bottom Layer w7.87: R46.1@8012.28,2570.87 R45.1@8012.28,2657.48 ; R45.1@8012.28,2658.71 8012.28,2690.05 8027.95,2705.71 C115.1@8181.1,2705.71 ; C115.1@8181.1,2706.69 v1(8181.1,2751.97)
TFT#.V9: LCD1.36 R44.2 | length 487
  Top Layer w7.87: v1(8141.73,2775.59) 8173.23,2807.09 8251.97,2807.09 8334.65,2724.41 8334.65,2692.91 8385.83,2641.73 LCD1.36@8448.82,2641.73
  Bottom Layer w7.87: R44.2@8061.81,2775.59 v1(8141.73,2775.59)
TFT#.VCOM: C114.1 LCD1.39 LCD1.40 VR1.2 | length 1897.6
  Top Layer w7.87: LCD1.39@8448.82,2700.79 8389.13,2700.79 8385.83,2704.09 v1(8385.83,2720.47) LCD1.40@8448.82,2720.47 ; v2(8708.66,1543.31) 8773.37,1543.31 VR1.2@8779.53,1549.47
  MidLayer1 w7.87: v1(8385.83,2720.47) 8385.83,2322.84 8271.65,2208.66 8271.65,1980.32 v2(8708.66,1543.31)
  Bottom Layer w7.87: v2(8708.66,1543.31) 8925.31,1543.31 8939.29,1557.29 C114.1@8939.29,1595.83
TFT#.X_MINUS: LCD1.49 U6.4 | length 960.7
  Top Layer w5: LCD1.49@8448.82,2897.64 8501.66,2897.64 8505.79,2901.76 8505.79,2934.21 8500,2940 8410,2940 8388.68,2961.32 8388.68,3212.45 8680.52,3504.29 U6.4@8757.87,3504.29
TFT#.X_PLUS: LCD1.47 U6.2 | length 964.4
  Top Layer w5: LCD1.47@8448.82,2858.27 8399.61,2858.27 8361.68,2896.2 8361.68,3224.45 8692.7,3555.47 U6.2@8757.87,3555.47
TFT#.Y_MINUS: LCD1.48 U6.5 | length 942.6
  Top Layer w5: LCD1.48@8448.82,2877.95 8503.18,2877.95 8518.68,2893.45 8518.68,2937.07 8502.3,2953.45 8425.68,2953.45 8402.68,2976.45 8402.68,3193.45 8687.93,3478.7 U6.5@8757.87,3478.7
TFT#.Y_PLUS: LCD1.50 U6.3 | length 880.4
  Top Layer w5: LCD1.50@8448.82,2917.32 8382.68,2917.32 8376.1,2923.9 8376.1,3217.88 8688.11,3529.88 U6.3@8757.87,3529.88
TFT.BLIGHT: R48.1 R49.1 U5.W12 | length 4549.9
  Top Layer w7.87: v1(9909.45,3208.66) U5.W12@9929.13,3228.35
  MidLayer2 w5: v1(7138.12,2172.51) 7209.6,2244 7475,2244 7774.12,1944.88 9059.06,1944.88 9149.61,2035.43 9149.61,2578.74 9318.9,2748.03 9862.2,2748.03 9929.13,2814.96 9929.13,2870.08 9929.13,2889.77 9929.13,3138.19 9917.72,3149.61 9900,3149.61 9889.76,3159.84 9889.76,3188.98 v1(9909.45,3208.66)
  Bottom Layer w5: R49.1@7154.34,2223.69 7154.34,2188.73 v1(7138.12,2172.51) 7161.74,2148.89 7460.88,2148.89 7473.23,2161.24 R48.1@7473.23,2223.69
TFT.IRQ: R47.1 U5.W2 U6.11 | length 1257.6
  Top Layer w5: v1(8963.71,3138.47) 9254.25,3138.47 9268.24,3152.46 9328.38,3212.6 9476.38,3212.6 9480.32,3208.66 9503.94,3208.66 9523.62,3228.35 U5.W2@9535.43,3228.35 ; U6.11@8976.38,3453.11 9274.33,3453.11 9401,3326.44 9401,3259.6 9448,3212.6
  Bottom Layer w5: R47.1@8962.56,3104.06 8962.88,3104.91 R47.1@8963.04,3105.33 ; R47.1@8963.04,3104.85 R47.1@8963.04,3105.33 ; v1(8963.71,3138.47) R47.1@8963.04,3105.33
TFT_SPI.BUSY: U5.U2 U6.13 | length 699.5
  Top Layer w5: U6.13@8976.38,3504.29 9251.43,3504.29 9421,3334.72 9421,3284.59 9430,3275.59 9448.14,3275.59 9463.89,3291.34 9480.32,3291.34 9484.25,3287.4 9503.94,3287.4 9523.62,3307.09 U5.U2@9535.43,3307.09
TFT_SPI.CLK: U5.R1 U6.16 | length 600.6
  Top Layer w5: U6.16@8976.38,3581.06 8976.65,3580.79 9217.36,3580.79 9404.69,3393.45 9463.21,3393.45 9470.84,3385.83 U5.R1@9496.06,3385.83
TFT_SPI.CS_N: U5.T1 U6.15 | length 606.3
  Top Layer w5: U6.15@8976.38,3555.47 9118.41,3555.47 9134,3539.88 9244.12,3539.88 9403.55,3380.45 9462.07,3380.45 U5.T1@9496.06,3346.46
TFT_SPI.DIN: U5.U1 U6.14 | length 612
  Top Layer w5: U6.14@8976.38,3529.88 9239.98,3529.88 9462.77,3307.09 U5.U1@9496.06,3307.09
TFT_SPI.DOUT: U5.W1 U6.12 | length 662.2
  Top Layer w5: U6.12@8976.38,3478.7 9262.88,3478.7 9411,3330.58 9411,3264.35 9447,3228.35 U5.W1@9496.06,3228.35
UBA#.DETECT: HDR1.10 R261.2 | length 345.4
  Bottom Layer w5: HDR1.10@3448.03,374.02 3531.5,374.02 3559.06,401.58 R261.2@3559.06,624.49
UBA#.HARD.TCK: HDR1.3 R251.2 | length 175.9
  Bottom Layer w5: R251.2@3086.61,624.49 3086.61,535.43 HDR1.3@3148.03,474.02
UBA#.HARD.TDI: HDR1.1 R248.2 | length 167.1
  Bottom Layer w5: R248.2@3007.87,624.49 3007.87,514.17 HDR1.1@3048.03,474.02
UBA#.HARD.TDO: HDR1.2 R249.2 | length 353.2
  Bottom Layer w5: R249.2@2929.13,624.49 2929.13,401.58 2956.69,374.02 HDR1.2@3048.03,374.02
UBA#.HARD.TMS: HDR1.4 R250.2 | length 283.7
  Bottom Layer w5: HDR1.4@3148.03,374.02 3196.85,422.83 3196.85,507.87 3165.35,539.37 R250.2@3165.35,624.49
UBA#.SOFT.TCK: HDR1.7 R259.2 | length 172.7
  Bottom Layer w5: HDR1.7@3348.03,474.02 3401.57,527.56 R259.2@3401.57,624.49
UBA#.SOFT.TDI: HDR1.5 R256.2 | length 152.1
  Bottom Layer w5: R256.2@3244.09,624.49 3244.09,477.95 HDR1.5@3248.03,474.02
UBA#.SOFT.TDO: HDR1.6 R257.2 | length 281.5
  Bottom Layer w5: HDR1.6@3248.03,374.02 3299.21,425.2 3299.21,507.87 3322.83,531.5 R257.2@3322.83,624.49
UBA#.SOFT.TMS: HDR1.8 R258.2 | length 383.5
  Bottom Layer w5: HDR1.8@3348.03,374.02 3397.02,423 3485.99,423 3511.81,448.82 3511.81,496.06 3480.32,527.56 R258.2@3480.32,624.49
UBA.DETECT: R260.1 R261.1 U5.Y19 | length 8921.5
  Top Layer w7.87: U5.Y19@10204.72,3188.98 v1(10224.41,3169.29)
  MidLayer3 w5: v2(3559.06,700.79) 3586.57,700.79 3625.95,661.42 3625.95,441.22 3834.88,232.28 4421.03,232.28 4610,421.26 6933.56,421.26 7720.47,1208.17 7720.47,1480.32 7964.57,1724.41 8688.98,1724.41 9027.56,2062.99 9027.56,2393.7 9295.28,2661.42 10095.28,2661.42 10244.09,2810.24 10244.09,2889.76 10244.1,3149.6 v1(10224.41,3169.29)
  Bottom Layer w11.81: R261.1@3559.06,666.85 v2(3559.06,700.79) R260.1@3559.06,764.25
UBA.HARD.TCK: R247.1 R251.1 U5.Y12 | length 8950.6
  Top Layer w7.87: v1(9909.45,3169.29) U5.Y12@9929.13,3188.98
  MidLayer3 w5: v2(3086.61,698.82) 3171.26,783.47 3604.12,783.47 3696.81,690.77 ; 3696.85,690.77 3696.85,470.53 3864.23,303.15 4391.67,303.15 4580.65,492.13 6904.21,492.13 7649.61,1237.52 7649.61,1509.67 7935.21,1795.28 8665.35,1795.28 8956.69,2086.61 8956.69,2417.32 9271.65,2732.28 9370.57,2732.28 9593.28,2955 9864.44,2955 9889.76,2980.32 9889.76,3149.6 v1(9909.45,3169.29)
  Bottom Layer w5: R251.1@3086.61,666.85 v2(3086.61,698.82) R247.1@3086.61,764.25
UBA.HARD.TDI: R244.1 R248.1 U5.Y11 | length 8992.7
  Top Layer w7.87: v1(9870.08,3169.29) U5.Y11@9889.76,3188.98
  MidLayer3 w5: v2(3007.87,698.82) 3104.33,795.28 3609.01,795.28 3708.62,695.66 3708.66,475.42 3870.94,313.15 4384.97,313.15 4575.76,503.94 6899.32,503.94 7637.8,1242.42 7637.8,1514.56 7930.32,1807.09 8661.42,1807.09 8944.88,2090.55 8944.88,2421.26 9267.72,2744.1 9368.24,2744.1 9589.14,2965 9835.07,2965 9850.39,2980.32 9850.39,3000 9850.39,3153.54 v1(9870.08,3169.29)
  Bottom Layer w5: R248.1@3007.87,666.85 v2(3007.87,698.82) R244.1@3007.87,764.25
UBA.HARD.TDO: R245.1 R249.1 U5.Y10 | length 9020.3
  Top Layer w7.87: v1(9830.71,3169.29) U5.Y10@9850.39,3188.98
  MidLayer3 w5: v2(2929.13,698.82) 3037.4,807.09 3613.9,807.09 3720.43,700.56 3720.43,480.36 3826.97,373.82 3877.64,323.15 4378.27,323.15 4570.87,515.75 6894.42,515.75 7625.98,1247.31 7625.98,1519.45 7925.43,1818.9 8657.48,1818.9 8933.07,2094.49 8933.07,2425.2 9263.78,2755.91 9365.91,2755.91 9585,2975 9785.12,2975 9811.02,3000.91 9811.02,3149.61 v1(9830.71,3169.29)
  Bottom Layer w5: R249.1@2929.13,666.85 v2(2929.13,698.82) R245.1@2929.13,764.25
UBA.HARD.TMS: R246.1 R250.1 U5.Y13 | length 8911.8
  Top Layer w7.87: v5@9948.82,3169.29 U5.Y13@9968.5,3188.98
  MidLayer3 w5: v2(3165.35,698.82) 3238.19,771.65 3599.23,771.65 3685,685.88 3685,465.68 3859.34,291.34 4396.57,291.34 4585.54,480.32 6909.1,480.32 7661.42,1232.63 7661.42,1504.78 7940.11,1783.47 8669.29,1783.47 8968.5,2082.68 8968.5,2413.39 9275.59,2720.47 9372.9,2720.47 9597.43,2945 9894.75,2945 9929.13,2979.39 9929.13,2998.31 9929.13,3149.6 9946.85,3167.32 v5@9948.82,3169.29
  Bottom Layer w5: R250.1@3165.35,666.85 v2(3165.35,698.82) R246.1@3165.35,764.25
  other v5: 9944.88,3169.29
UBA.SOFT.TCK: R255.1 R259.1 U5.Y17 | length 9085.2
  Top Layer w7.87: U5.Y17@10125.98,3188.98 v1(10145.67,3169.29)
  MidLayer3 w5: v2(3401.57,700.79) 3437,736.22 3584.55,736.22 3649.57,671.2 3649.57,451 3844.66,255.91 4411.24,255.91 4600.22,444.88 6923.78,444.88 7696.85,1217.95 7696.85,1490.1 7954.78,1748.03 8681.1,1748.03 9003.94,2070.87 9003.94,2401.58 9287.4,2685.04 10090.61,2685.04 10209.68,2804.11 10209.68,2966.82 10192.25,2984.25 10177,2984.25 10165.35,2995.9 10165.35,3149.61 v1(10145.67,3169.29)
  Bottom Layer w5: R259.1@3401.57,666.85 R255.1@3401.57,764.25
UBA.SOFT.TDI: R252.1 R256.1 U5.Y14 | length 9222.5
  Top Layer w7.87: U5.Y14@10007.87,3188.98 v5@10027.56,3169.29
  MidLayer3 w5: v2@3244.09,698.82 3305.11,759.84 3594.33,759.84 3673.19,680.99 3673.19,460.79 3854.45,279.53 4401.46,279.53 4590.44,468.5 6913.99,468.5 7673.23,1227.74 7673.23,1499.88 7945,1771.65 8673.23,1771.65 8980.32,2078.74 8980.32,2409.45 9279.53,2708.66 9984.25,2708.66 10035.68,2760.09 10123.24,2760.09 10166,2802.85 10166,2826 10109,2883 10109,2909.78 10047.24,2971.53 10047.25,3149.6 10029.53,3167.32 v5@10027.56,3169.29
  Bottom Layer w5: R256.1@3244.09,666.85 v2(3244.09,698.82) R252.1@3244.09,764.25
  other v5: 10031.5,3169.29
UBA.SOFT.TDO: R253.1 R257.1 U5.Y16 | length 9165.6
  Top Layer w7.87: U5.Y16@10086.61,3188.98 v1(10106.3,3169.29)
  MidLayer3 w5: v2(3322.83,700.79) 3370.08,748.03 3589.44,748.03 3661.38,676.09 3661.42,455.85 3849.55,267.72 4406.35,267.72 4595.33,456.69 6918.89,456.69 7685.04,1222.85 7685.04,1494.99 7949.89,1759.84 8677.17,1759.84 8992.13,2074.8 8992.13,2405.51 9283.46,2696.85 10088.28,2696.85 10194.82,2803.39 10194.82,2931.31 10159.13,2967 10136,2967 10125.99,2977.01 10125.99,3000 10125.98,3153.54 v1(10106.3,3169.29)
  Bottom Layer w5: R257.1@3322.83,666.85 v2(3322.83,700.79) R253.1@3322.83,764.25
UBA.SOFT.TMS: R254.1 R258.1 U5.Y18 | length 9001.7
  Top Layer w7.87: U5.Y18@10165.35,3188.98 v1(10185.04,3169.29)
  MidLayer3 w5: v2(3480.32,700.79) 3503.93,724.41 3579.66,724.41 3637.76,666.31 3637.76,446.11 3839.77,244.1 4417.09,244.1 4606.07,433.07 6928.67,433.07 7708.66,1213.06 7708.66,1485.21 7959.67,1736.22 8685.04,1736.22 9015.75,2066.93 9015.75,2397.64 9291.34,2673.23 10092.95,2673.23 10224.41,2804.69 10224.41,2972.44 10204.73,2992.13 10204.73,3149.6 v1(10185.04,3169.29)
  Bottom Layer w5: R258.1@3480.32,666.85 v2(3480.32,700.79) R254.1@3480.32,764.25
UBB#.DETECT: HDR2.10 R279.2 | length 347.9
  Bottom Layer w5: HDR2.10@4353.54,374.02 4433.07,374.02 4464.57,405.51 R279.2@4464.57,622.52
  Bottom Layer w10: R279.2@4464.57,622.52 R279.2@4471.42,622.52
UBB#.HARD.TCK: HDR2.3 R269.2 | length 173.9
  Bottom Layer w5: R269.2@3992.13,622.52 3992.13,535.43 HDR2.3@4053.54,474.02
UBB#.HARD.TDI: HDR2.1 R266.2 | length 165.1
  Bottom Layer w5: R266.2@3913.39,622.52 3913.39,514.17 HDR2.1@3953.54,474.02
UBB#.HARD.TDO: HDR2.2 R267.2 | length 351.3
  Bottom Layer w5: R267.2@3834.65,622.52 3834.65,401.57 3862.2,374.02 HDR2.2@3953.54,374.02
UBB#.HARD.TMS: HDR2.4 R268.2 | length 281.8
  Bottom Layer w5: HDR2.4@4053.54,374.02 4102.36,422.83 4102.36,507.87 4070.87,539.37 R268.2@4070.87,622.52
UBB#.SOFT.TCK: HDR2.7 R277.2 | length 170.7
  Bottom Layer w5: HDR2.7@4253.54,474.02 4307.09,527.56 R277.2@4307.09,622.52
UBB#.SOFT.TDI: HDR2.5 R274.2 | length 155.7
  Bottom Layer w5: R274.2@4149.61,622.52 4149.61,477.95 HDR2.5@4153.54,474.02
  Bottom Layer w11.81: R274.2@4149.61,622.52 R274.2@4153.54,618.58
UBB#.SOFT.TDO: HDR2.6 R275.2 | length 279.5
  Bottom Layer w5: HDR2.6@4153.54,374.02 4204.72,425.2 4204.72,507.87 4228.35,531.5 R275.2@4228.35,622.52
UBB#.SOFT.TMS: HDR2.8 R276.2 | length 381.5
  Bottom Layer w5: HDR2.8@4253.54,374.02 4303.53,424 4392.5,424 4417.32,448.82 4417.32,496.06 4385.83,527.56 R276.2@4385.83,622.52
UBB.DETECT: R278.1 R279.1 U5.P7 | length 7128.2
  Top Layer w7.87: v5@9712.6,3405.51 U5.P7@9732.28,3425.2
  MidLayer3 w5: v2(4464.57,700.79) 4543.31,622.05 6850.39,622.05 7519.69,1291.34 7519.69,1563.48 7881.4,1925.2 8622.05,1925.2 8811.02,2114.17 8811.02,2704.49 9345.51,3238.98 9489.5,3238.98 9502,3251.48 9502,3359.96 9527.87,3385.83 9692.91,3385.83 v5@9711.61,3404.53
  Bottom Layer w11.81: R279.1@4464.57,664.88 v2(4464.57,700.79) R278.1@4464.57,764.25
  other v5: 9710.63,3405.51
UBB.HARD.TCK: R265.1 R269.1 U5.Y7 | length 7495.2
  Top Layer w7.87: v1(9712.6,3169.29) U5.Y7@9732.28,3188.98
  MidLayer3 w5: v2(3992.13,698.82) 4139.76,551.18 6879.75,551.18 7590.55,1261.99 7590.55,1534.13 7910.75,1854.33 8645.67,1854.33 8881.89,2090.55 8881.89,2675.14 9356.36,3149.61 9413.39,3149.61 9433.07,3149.61 9692.91,3149.61 v1(9712.6,3169.29)
  Bottom Layer w5: R269.1@3992.13,664.88 v2(3992.13,698.82) R265.1@3992.13,764.25
UBB.HARD.TDI: R262.1 R266.1 U5.Y8 | length 7658.8
  Top Layer w7.87: v1(9751.97,3169.29) U5.Y8@9771.65,3188.98
  MidLayer3 w5: v2(3913.39,698.82) 4072.83,539.37 6884.64,539.37 7602.36,1257.09 7602.36,1529.24 7915.64,1842.52 8649.61,1842.52 8893.7,2086.61 8893.7,2670.25 9227.87,3004.42 ; 9213.58,2990.12 9333.69,3110.24 9413.39,3110.24 9433.07,3110.24 9720.47,3110.24 9732.28,3122.05 9732.28,3149.6 v1(9751.97,3169.29)
  Bottom Layer w5: R266.1@3913.39,664.88 v2(3913.39,698.82) R262.1@3913.39,764.25
UBB.HARD.TDO: R263.1 R267.1 U5.Y9 | length 7814.2
  Top Layer w7.87: v1(9791.34,3169.29) U5.Y9@9811.02,3188.98
  MidLayer3 w5: v2(3834.65,698.82) 4005.91,527.56 6889.53,527.56 7614.17,1252.2 7614.17,1524.35 7920.54,1830.71 8653.54,1830.71 8905.51,2082.68 8905.51,2665.36 9338.58,3098.43 9413.39,3098.43 9433.07,3098.43 9507.87,3098.43 9535.43,3070.87 9763.78,3070.87 9771.65,3078.74 9771.65,3149.6 v1(9791.34,3169.29)
  Bottom Layer w5: R267.1@3834.65,664.88 v2(3834.65,698.82) R263.1@3834.65,764.25
UBB.HARD.TMS: R264.1 R268.1 U5.W7 | length 7423.5
  Top Layer w7.87: v1(9712.6,3208.66) U5.W7@9732.28,3228.35
  MidLayer3 w5: v2(4070.87,698.82) 4206.69,562.99 6874.86,562.99 7578.74,1266.88 7578.74,1539.02 7905.86,1866.14 8641.73,1866.14 8870.08,2094.49 8870.08,2680.03 9379.02,3188.98 9409.45,3188.98 9433.07,3188.98 9692.91,3188.98 v1(9712.6,3208.66)
  Bottom Layer w5: R268.1@4070.87,664.88 v2(4070.87,698.82) R264.1@4070.87,764.25
UBB.SOFT.TCK: R273.1 R277.1 U5.T7 | length 7235.6
  Top Layer w7.87: v1(9712.6,3326.77) U5.T7@9732.28,3346.46
  MidLayer3 w5: v2(4307.09,700.79) 4409.45,598.43 6860.18,598.43 7543.31,1281.55 7543.31,1553.7 7891.18,1901.58 8629.92,1901.58 8834.65,2106.3 8834.65,2694.71 9358.91,3218.98 9497.78,3218.98 9522,3243.2 9522,3285.78 9543.31,3307.09 9696.85,3307.09 v1(9712.6,3326.77)
  Bottom Layer w5: R277.1@4307.09,664.88 v2(4307.09,700.79) R273.1@4307.09,764.25
UBB.SOFT.TDI: R270.1 R274.1 U5.V7 | length 7351.8
  Top Layer w7.87: v1(9712.6,3248.03) U5.V7@9732.28,3267.72
  MidLayer3 w5: v2(4149.61,698.82) 4273.62,574.8 6869.96,574.8 7566.93,1271.77 7566.93,1543.92 7900.97,1877.95 8637.8,1877.95 8858.27,2098.43 8858.27,2684.92 9372.32,3198.98 9506.07,3198.98 9535.43,3228.35 9692.91,3228.35 v1(9712.6,3248.03)
  Bottom Layer w5: R274.1@4149.61,664.88 v2(4149.61,698.82) R270.1@4149.61,764.25
UBB.SOFT.TDO: R271.1 R275.1 U5.U7 | length 7290.8
  Top Layer w7.87: v1(9712.6,3287.4) U5.U7@9732.28,3307.09
  MidLayer3 w5: v2(4228.35,700.79) 4342.52,586.62 6865.07,586.62 7555.12,1276.66 7555.12,1548.81 7896.08,1889.76 8633.86,1889.76 8846.46,2102.36 8846.46,2689.82 9365.62,3208.98 9501.92,3208.98 9532,3239.05 9532,3255.72 9544,3267.72 9692.91,3267.72 v1(9712.6,3287.4)
  Bottom Layer w5: R275.1@4228.35,664.88 v2(4228.35,700.79) R271.1@4228.35,764.25
UBB.SOFT.TMS: R272.1 R276.1 U5.R7 | length 7188.9
  Top Layer w7.87: v1(9712.6,3366.14) U5.R7@9732.28,3385.83
  MidLayer3 w5: v2(4385.83,700.79) 4476.38,610.24 6855.29,610.24 7531.5,1286.45 7531.5,1558.59 7886.29,1913.39 8625.98,1913.39 8822.83,2110.24 8822.83,2699.6 9352.21,3228.98 9493.64,3228.98 9512,3247.34 9512,3334.83 9523.62,3346.46 9692.91,3346.46 v1(9712.6,3366.14)
  Bottom Layer w5: R276.1@4385.83,664.88 v2(4385.83,700.79) R272.1@4385.83,764.25
UGCLK0: U5.B13
UGCLK1: U5.A13
UGCLK2: U5.C14 | length 27.8
  Top Layer w7.87: U5.C14@10007.87,3858.27 v1(10027.56,3877.95)
UGCLK3: U5.B14 | length 27.8
  Top Layer w5: U5.B14@10007.87,3897.64 v1(10027.56,3917.32)
UGCLK4: U5.AE14
UIO.IO0: HDR_B1.7 UH1.2 | length 1478.4
  Top Layer w7.87: UH1.2@5866.14,351.97 5866.14,403.94 6084.25,622.05 6450.77,622.05 6582.68,753.96 HDR_B1.7@6582.68,1318.9
UIO.IO1: HDR_B1.9 UH1.3 | length 1575.9
  Top Layer w7.87: UH1.3@5966.14,251.97 5916.14,301.97 5916.14,401.18 6118.5,603.54 6458.43,603.54 6614.17,759.29 HDR_B1.9@6614.17,1318.9
UIO.IO2: HDR_B1.11 UH1.4 | length 1433.3
  Top Layer w7.87: UH1.4@5966.14,351.97 5966.14,400.79 6150.39,585.04 6466.1,585.04 6641.73,760.68 6641.73,1251.97 6645.67,1255.91 HDR_B1.11@6645.67,1318.9
UIO.IO3: HDR_B1.13 UH1.5 | length 1532.6
  Top Layer w7.87: UH1.5@6066.14,251.97 6016.14,301.97 6016.14,401.18 6181.5,566.54 6473.76,566.54 6661.42,754.19 6661.42,1240.16 6677.16,1255.91 HDR_B1.13@6677.16,1318.9
UIO.IO4: HDR_B1.15 UH1.6 | length 1390.1
  Top Layer w7.87: UH1.6@6066.14,351.97 6066.14,400.79 6213.39,548.03 6481.42,548.03 6681.1,747.71 6681.1,1228.35 6708.66,1255.91 HDR_B1.15@6708.66,1318.9
UIO.IO5: HDR_B1.17 UH1.7 | length 1491.2
  Top Layer w7.87: UH1.7@6166.14,251.97 6116.14,301.97 6116.14,401.18 6243.7,528.74 6491.32,528.74 6700.79,738.21 6700.79,1216.54 6740.16,1255.91 HDR_B1.17@6740.16,1318.9
UIO.IO6: HDR_B1.19 UH1.8 | length 1348.3
  Top Layer w7.87: UH1.8@6166.14,351.97 6166.14,400.79 6275.98,510.63 6498.82,510.63 6720.47,732.28 6720.47,1204.73 6771.65,1255.91 HDR_B1.19@6771.65,1318.9
UIO.IO7: HDR_B1.21 UH1.9 | length 1446.1
  Top Layer w7.87: UH1.9@6266.14,251.97 6216.14,301.97 6216.14,401.18 6307.09,492.13 6503.94,492.13 6740.16,728.35 6740.16,1192.91 6803.15,1255.91 HDR_B1.21@6803.15,1318.9
UIO.IO8: HDR_B1.23 UH1.10 | length 1309
  Top Layer w7.87: UH1.10@6266.14,351.97 6266.14,408.67 6329.92,472.44 6511.81,472.44 6759.84,720.47 6759.84,1181.1 6834.65,1255.91 HDR_B1.23@6834.65,1318.9
UIO.IO9: HDR_B1.25 UH1.11 | length 1400.1
  Top Layer w7.87: UH1.11@6366.14,251.97 6316.14,301.97 6316.14,393.7 6375.2,452.76 6519.69,452.76 6779.53,712.6 6779.53,1169.29 6866.14,1255.91 HDR_B1.25@6866.14,1318.9
UIO.IO10: HDR_B1.27 UH1.12 | length 1258.6
  Top Layer w7.87: UH1.12@6366.14,351.97 6366.14,393.7 6405.51,433.07 6527.56,433.07 6799.21,704.73 6799.21,1157.48 6897.64,1255.91 HDR_B1.27@6897.64,1318.9
UIO.IO11: HDR_B1.29 UH1.13 | length 1351.6
  Top Layer w7.87: UH1.13@6466.14,251.97 6416.14,301.97 6416.14,381.89 6447.64,413.39 6535.43,413.39 6818.9,696.85 6818.9,1145.67 6929.13,1255.91 HDR_B1.29@6929.13,1318.9
UIO.IO12: HDR_B1.31 UH1.14 | length 1192.5
  Top Layer w7.87: UH1.14@6466.14,351.97 6507.87,393.7 6543.31,393.7 6838.58,688.98 6838.58,1141.73 6960.63,1263.78 HDR_B1.31@6960.63,1318.9
UIO.IO13: HDR_B1.33 UH1.15 | length 1917.9
  Top Layer w7.87: v4(6408.68,1373.45) 6428.93,1393.7 6984.25,1393.7 6992.13,1385.83 HDR_B1.33@6992.13,1318.9
  MidLayer1 w7.87: v4(6408.68,1373.45) 6457.26,1373.45 6615.26,1215.45 6615.26,301.09 UH1.15@6566.14,251.97
UIO.IO14: HDR_B1.35 UH1.16 | length 1416.5
  Top Layer w7.87: UH1.16@6566.14,351.97 6631.5,417.32 6842.52,417.32 6905.51,480.32 6988.19,480.32 7129.92,622.05 7129.92,1149.61 7023.62,1255.91 HDR_B1.35@7023.62,1318.9
UIO.IO15: HDR_B1.37 UH1.17 | length 1523.3
  Top Layer w7.87: 6615.35,304.33 6615.35,367.32 6645.67,397.64 6850.39,397.64 6897.64,444.88 6909.45,456.69 7007.87,456.69 7149.61,598.43 7149.61,1161.42 7125.88,1185.14 7055.12,1255.91 HDR_B1.37@7055.12,1318.9 ; 6616.14,301.97 UH1.17@6666.14,251.97
UIO.IO16: HDR_B1.39 UH1.18 | length 1411.9
  Top Layer w7.87: UH1.18@6666.14,351.97 6714.96,303.15 6787.4,303.15 6917.32,433.07 7023.62,433.07 7169.29,578.74 7169.29,1173.23 7086.61,1255.91 HDR_B1.39@7086.61,1318.9
UIO.IO17: HDR_B1.41 UH1.19 | length 1341.5
  Top Layer w7.87: UH1.19@6766.14,251.97 6923.62,409.45 7043.31,409.45 7188.98,555.12 7188.98,1185.04 7118.11,1255.91 HDR_B1.41@7118.11,1318.9
UIO.IO18: HDR_B1.43 UH2.2 | length 1014.2
  Top Layer w7.87: HDR_B1.43@7149.61,1318.9 7149.61,1255.91 7208.66,1196.85 7208.66,555.12 7263.78,500 UH2.2@7263.78,351.97
UIO.IO19: HDR_B1.45 UH2.3 | length 1142.6
  Top Layer w7.87: HDR_B1.45@7181.1,1318.9 7181.1,1255.91 7228.35,1208.66 7228.35,580.51 7313.78,495.07 7313.78,301.97 UH2.3@7363.78,251.97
